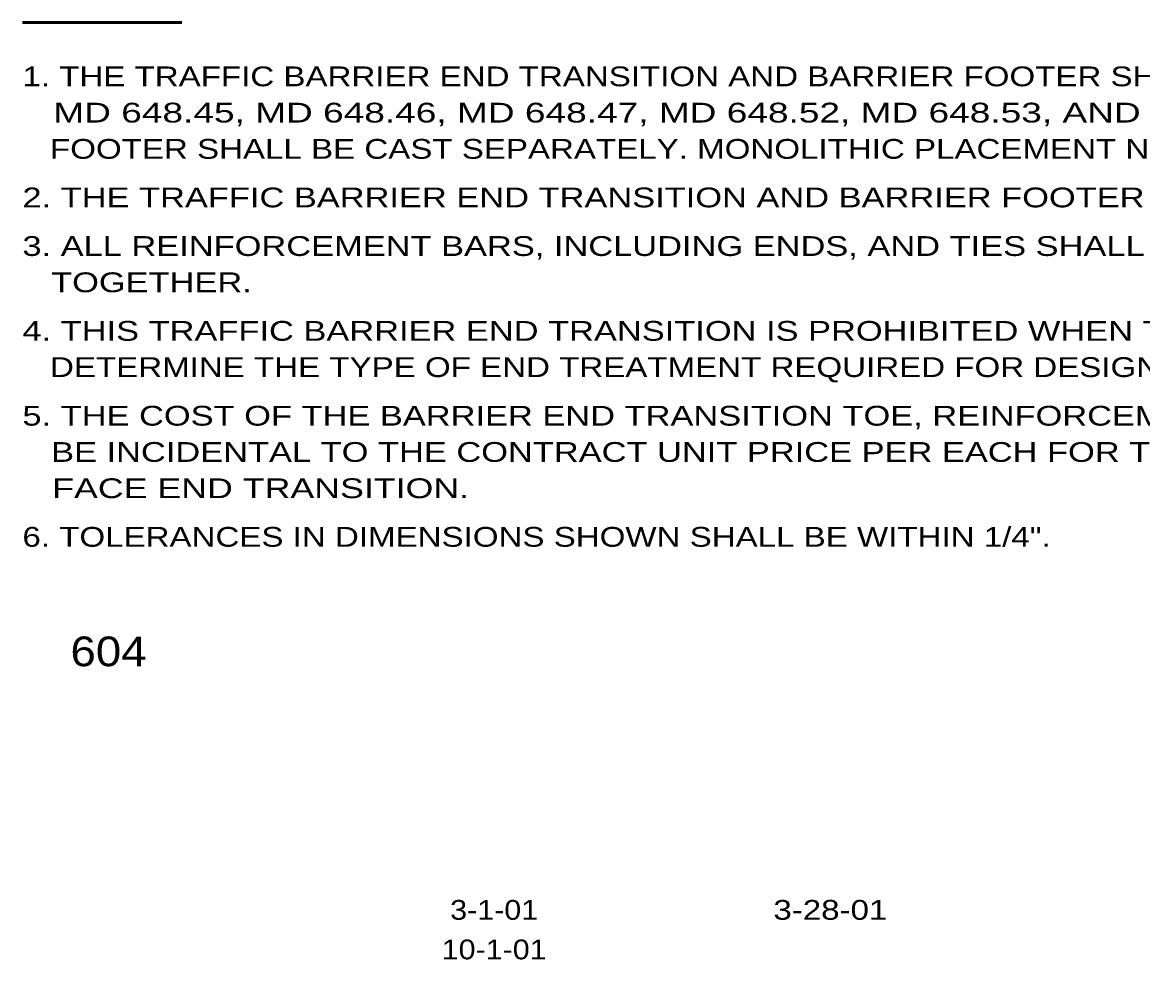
# Model space of a CAD drawing. Extents: x -15.1 to -7.9, y 13.6 to 23.8.
# Drawn here: x -15.091 to -11.694, y 13.802 to 16.645 of the extents above; entities that cross this region are included whole.
import ezdxf
from ezdxf.enums import TextEntityAlignment as Align

# ---------------------------------------------------------------- set-up
doc = ezdxf.new("R2010")
doc.units = 0
doc.header["$LTSCALE"] = 0.024
doc.layers.add('13', color=7, linetype='Continuous', lineweight=53)

msp = doc.modelspace()

# ---------------------------------------------------------------- linework, layer by layer
at = {"layer": '13'}
msp.add_line((-15.0905, 16.64542), (-14.6075, 16.64542), dxfattribs=at)

# ---------------------------------------------------------------- texts
for s, width, p in [('1. THE TRAFFIC BARRIER END TRANSITION AND BARRIER FOOTER SHALL BE CONSTRUCTED USING THE FIXED FORM METHOD. SEE STDS.', 1.25, (-15.09042, 16.45167)), ('   MD 648.45, MD 648.46, MD 648.47, MD 648.52, MD 648.53, AND MD 648.54 FOR BARRIER FOOTER DETAILS. THE BARRIER AND', 1.4, (-15.09042, 16.34167)), ('   FOOTER SHALL BE CAST SEPARATELY. MONOLITHIC PLACEMENT NOT PERMITTED.', 1.25, (-15.09042, 16.23167)), ('2. THE TRAFFIC BARRIER END TRANSITION AND BARRIER FOOTER SHALL BE CONSTRUCTED USING CONCRETE MIX NO.6 (4500 PSI).', 1.3, (-15.09042, 16.08433)), ('3. ALL REINFORCEMENT BARS, INCLUDING ENDS, AND TIES SHALL BE EPOXY COATED. ALL BAR LAPS TO BE 30 BAR DIAMETERS. TIE BARS', 1.3, (-15.09042, 15.93692)), ('   TOGETHER.', 1.3, (-15.09042, 15.82692)), ('4. THIS TRAFFIC BARRIER END TRANSITION IS PROHIBITED WHEN THE DESIGN SPEED IS 45 MPH OR GREATER. THE ENGINEER MUST', 1.3, (-15.09042, 15.67958)), ('   DETERMINE THE TYPE OF END TREATMENT REQUIRED FOR DESIGN SPEEDS OVER 45 MPH.', 1.25, (-15.09042, 15.56958)), ('5. THE COST OF THE BARRIER END TRANSITION TOE, REINFORCEMENT, DRILLED HOLES, GROUT, LABOR, TOOLS, EQUIPMENT, ETC., SHALL', 1.3, (-15.09042, 15.42217)), ('   BE INCIDENTAL TO THE CONTRACT UNIT PRICE PER EACH FOR THE 34 INCH OR 42 INCH F SHAPE CONCRETE TRAFFIC BARRIER SINGLE', 1.3, (-15.09042, 15.31217)), ('   FACE END TRANSITION.', 1.35, (-15.09042, 15.20217)), ('6. TOLERANCES IN DIMENSIONS SHOWN SHALL BE WITHIN 1/4".', 1.25, (-15.09042, 15.05475))]:
    msp.add_text(s, height=0.06001, dxfattribs=dict(at, width=width)).set_placement(p)
for s, height, width, p in [('604', 0.09001, 1.15, (-14.82929, 14.69225)), ('3-1-01', 0.06, 1.15, (-13.66008, 13.92308)), ('3-28-01', 0.06, 1.25, (-12.64062, 13.92308)), ('10-1-01', 0.06, 1.15, (-13.66008, 13.80308))]:
    msp.add_text(s, height=height, dxfattribs=dict(at, width=width)).set_placement(p, align=Align.CENTER)

doc.saveas('drawing.dxf')
